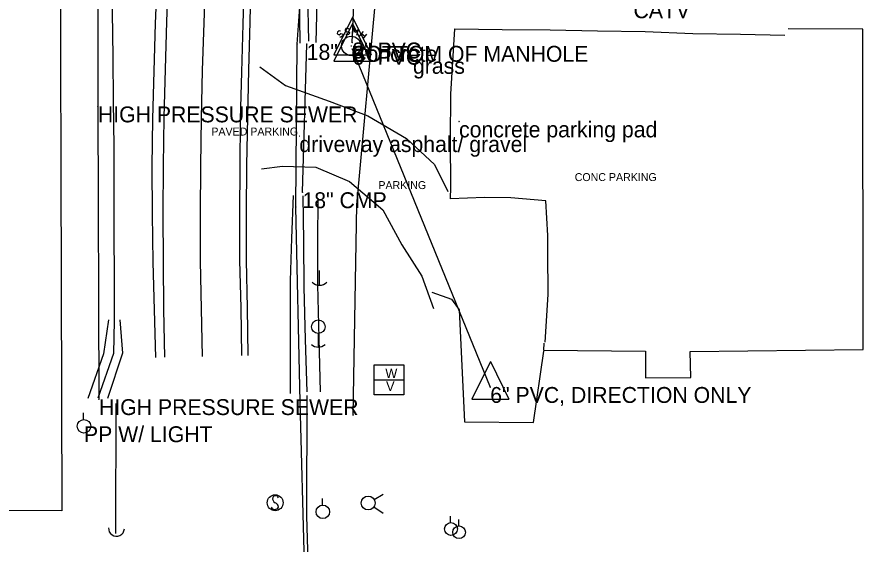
# Model space of a CAD drawing. Extents: x 1802180 to 1804859, y 572524 to 575172.
# Drawn here: x 1803144.4 to 1803410.8, y 572716.2 to 572882.1 of the extents above; entities that cross this region are included whole.
import ezdxf

# ---------------------------------------------------------------- set-up
doc = ezdxf.new("R2010")
doc.units = 0
for name, color, linetype in [('EX_EDGE_PAVEMENT', 7, 'Continuous'), ('S_CAL_CORNER', 7, 'Continuous'), ('S_CROSS_DRAIN', 7, 'Continuous'), ('S_DITCHLINE', 7, 'Continuous'), ('S_DRG_PT_SYM', 7, 'Continuous'), ('S_DRIVEWAY', 7, 'Continuous'), ('S_EDGE_CONCRETE', 7, 'Continuous'), ('S_GAS_UTILITIES', 7, 'Continuous'), ('S_MANHOLE_ANNOT', 7, 'Continuous'), ('S_MISC_BOUNDARY', 7, 'Continuous'), ('S_MSC_PT_SYM', 7, 'Continuous'), ('S_PARKING', 7, 'Continuous'), ('S_PARKING_ANNOT', 7, 'Continuous'), ('S_PAVEMENT_CROWN', 7, 'Continuous'), ('S_SANITARY_SEWER', 7, 'Continuous'), ('S_SANITARY_SEWER_ANNOT', 7, 'Continuous'), ('S_SHOULDER', 7, 'Continuous'), ('S_SIDE_DRAIN', 7, 'Continuous'), ('S_SIDE_DRAIN_ANNOT', 7, 'Continuous'), ('S_SIGN', 7, 'Continuous'), ('S_STREAM', 7, 'Continuous'), ('S_SURVEY_TEXT_ANNOT', 7, 'Continuous'), ('S_TELEPHONE_UTILITIES_ANNOT', 7, 'Continuous'), ('S_UTILITY_POLE', 7, 'Continuous'), ('S_UTILITY_POLE_ANNOT', 7, 'Continuous'), ('S_UTL_PT_SYM', 7, 'Continuous'), ('S_WATER_UTILITIES', 7, 'Continuous')]:
    doc.layers.add(name, color=color, linetype=linetype)

msp = doc.modelspace()

# ---------------------------------------------------------------- linework, layer by layer
at = {"layer": 'EX_EDGE_PAVEMENT'}
for points in [[(1803190.96, 572775), (1803190.67, 572789.99), (1803190.52, 572805.05), (1803190.47, 572820.24), (1803190.56, 572835.38), (1803190.74, 572850.48), (1803191.11, 572865.67), (1803191.56, 572880.57), (1803192.13, 572895.93), (1803192.98, 572910.91), (1803194.03, 572925.97), (1803195.31, 572941.25), (1803196.89, 572956.4), (1803198.72, 572971.29), (1803200.89, 572986.62), (1803203.33, 573001.42), (1803205.96, 573016.44)], [(1803229.77, 573012.09), (1803227.31, 572997.57), (1803224.82, 572982.77), (1803222.69, 572968.45), (1803220.88, 572953.56), (1803219.24, 572938.89), (1803217.94, 572924.29), (1803216.81, 572909.44), (1803215.9, 572894.47), (1803215.53, 572879.86), (1803215.04, 572864.77), (1803214.7, 572849.98), (1803214.58, 572835.08), (1803214.46, 572820.23), (1803214.48, 572805.43), (1803214.88, 572790.5), (1803215.12, 572775.5)]]:
    msp.add_lwpolyline(points, dxfattribs=at)
at = {"layer": 'S_CAL_CORNER'}
for p, q in [((1803250.06, 572882.03), (1803244.18, 572870.21)), ((1803250.06, 572882.03), (1803255.87, 572870.21)), ((1803250.07, 572880.04), (1803244.2, 572868.22)), ((1803250.07, 572880.04), (1803255.89, 572868.22)), ((1803244.18, 572870.21), (1803255.87, 572870.21)), ((1803244.2, 572868.22), (1803255.89, 572868.22)), ((1803293.5, 572773.61), (1803287.62, 572761.79)), ((1803293.5, 572773.61), (1803299.31, 572761.79)), ((1803287.62, 572761.79), (1803299.31, 572761.79))]:
    msp.add_line(p, q, dxfattribs=at)
at = {"layer": 'S_CROSS_DRAIN'}
msp.add_arc((1803175.71, 572721.17), 2.5, 175.9715, 356.3007, dxfattribs=at)
at = {"layer": 'S_DITCHLINE'}
for points in [[(1803191.07, 573030.48), (1803186.39, 573007.51), (1803182.91, 572995.28), (1803179.43, 572983.05), (1803177.62, 572967.17), (1803175.82, 572951.28), (1803175.41, 572937.89), (1803175, 572924.5), (1803174.59, 572911.11), (1803174.18, 572897.72), (1803174.36, 572883.63), (1803174.53, 572869.54), (1803174.71, 572855.44), (1803174.88, 572841.35), (1803174.91, 572827.64), (1803174.93, 572813.93), (1803174.96, 572800.22), (1803174.98, 572786.51), (1803174.73, 572776.19), (1803169.82, 572762.15)], [(1803233.51, 572873.82), (1803233.22, 572897.98), (1803232.93, 572922.13), (1803234.68, 572936.13), (1803236.43, 572950.13), (1803238.18, 572964.13), (1803239.93, 572978.13), (1803245.22, 572978.79), (1803243.9, 572965.52), (1803242.57, 572952.24), (1803241.24, 572938.96), (1803239.92, 572925.69), (1803239.56, 572912.78), (1803239.2, 572899.88), (1803238.85, 572886.98), (1803238.49, 572874.08)], [(1803236.24, 572874.49), (1803236.01, 572889.51), (1803235.77, 572904.52), (1803237.65, 572923.02), (1803239.52, 572941.52), (1803241.39, 572960.03), (1803243.27, 572978.53)], [(1803230.47, 572763.54), (1803230.47, 572781.28), (1803230.47, 572799.02), (1803230.97, 572812.47), (1803231.47, 572825.91)], [(1803235.72, 572764.15), (1803235.27, 572780.61), (1803234.82, 572797.08), (1803234.66, 572811.43), (1803234.5, 572825.79)], [(1803239.92, 572764.15), (1803239.51, 572780.96), (1803239.09, 572797.77), (1803239.17, 572811.39), (1803239.26, 572825.02)], [(1803173.21, 572786.75), (1803171.64, 572776.07), (1803166.65, 572762.03)], [(1803176.73, 572786.81), (1803177.62, 572776.32), (1803172.87, 572761.98)]]:
    msp.add_lwpolyline(points, dxfattribs=at)
at = {"layer": 'S_DRG_PT_SYM'}
for points in [[(1803235.61, 572873.58), (1803235.61, 572873.63), (1803235.61, 572873.58), (1803235.56, 572873.58), (1803235.61, 572873.58), (1803235.61, 572873.53), (1803235.61, 572873.58), (1803235.66, 572873.58)], [(1803234.28, 572826.92), (1803234.28, 572826.97), (1803234.28, 572826.92), (1803234.23, 572826.92), (1803234.28, 572826.92), (1803234.28, 572826.87), (1803234.28, 572826.92), (1803234.33, 572826.92)]]:
    msp.add_lwpolyline(points, dxfattribs=at)
at = {"layer": 'S_DRIVEWAY'}
for points in [[(1803220.82, 572866.42), (1803228.99, 572860.55), (1803242.69, 572855.6), (1803254.84, 572851.01), (1803267.09, 572843.85), (1803275.87, 572835.62), (1803280.1, 572827.12)], [(1803221.41, 572834.28), (1803228.01, 572835.09), (1803238.54, 572834.78), (1803249.05, 572830.36), (1803259.62, 572821.4), (1803265.55, 572810.43), (1803271.85, 572800.55), (1803275.51, 572790.3)]]:
    msp.add_lwpolyline(points, dxfattribs=at)
at = {"layer": 'S_EDGE_CONCRETE'}
msp.add_lwpolyline([(1803310.71, 572779.78), (1803311.69, 572794.76), (1803311.58, 572807.87), (1803311.51, 572813.36), (1803310.95, 572824.26), (1803299.9, 572825.13), (1803291.56, 572825.27), (1803280.86, 572824.89), (1803281.03, 572828.54), (1803280.86, 572843.54), (1803280.95, 572857.79), (1803282.25, 572878.37), (1803297.21, 572878.13), (1803312.23, 572878.09), (1803327.23, 572877.77), (1803342.23, 572877.52), (1803357.22, 572876.93), (1803372.2, 572876.67), (1803386.12, 572876.33)], dxfattribs=at)
at = {"layer": 'S_GAS_UTILITIES'}
for p, q in [((1803232.66, 572873.56), (1803239.64, 572977.11)), ((1803232.24, 572822.25), (1803232.66, 572873.56)), ((1803233.57, 572760.94), (1803232.24, 572822.25)), ((1803235.4, 572692.72), (1803233.57, 572760.94))]:
    msp.add_line(p, q, dxfattribs=at)
at = {"layer": 'S_MISC_BOUNDARY'}
msp.add_lwpolyline([(1802880.88, 573735.6), (1803051.71, 573733.48), (1803213.27, 573730.83), (1803216.46, 573532.09), (1803301.63, 573530.07), (1803296.75, 573432.28), (1803274.96, 573355.36), (1803226.68, 573219.53), (1803202.19, 573137.5), (1803157.77, 572977.33), (1803158.5, 572726.69), (1802889.88, 572728.1)], dxfattribs=at)
at = {"layer": 'S_MSC_PT_SYM'}
for points in [[(1803269.08, 572869.21), (1803269.08, 572869.26), (1803269.08, 572869.21), (1803269.03, 572869.21), (1803269.08, 572869.21), (1803269.08, 572869.16), (1803269.08, 572869.21), (1803269.13, 572869.21)], [(1803283.58, 572849.2), (1803283.58, 572849.25), (1803283.58, 572849.2), (1803283.53, 572849.2), (1803283.58, 572849.2), (1803283.58, 572849.15), (1803283.58, 572849.2), (1803283.63, 572849.2)], [(1803233.3, 572844.58), (1803233.3, 572844.63), (1803233.3, 572844.58), (1803233.25, 572844.58), (1803233.3, 572844.58), (1803233.3, 572844.53), (1803233.3, 572844.58), (1803233.35, 572844.58)]]:
    msp.add_lwpolyline(points, dxfattribs=at)
at = {"layer": 'S_PARKING'}
for points in [[(1803410.81, 572777.43), (1803410.71, 572878.28), (1803387.24, 572878.36)], [(1803275, 572795.47), (1803281.17, 572793.24), (1803283.63, 572789.91), (1803285.33, 572754.66), (1803307.06, 572754.43), (1803310.26, 572776.94)], [(1803310.24, 572779.44), (1803310.23, 572777.19), (1803342.25, 572776.94), (1803342.29, 572768.49), (1803356.61, 572768.6), (1803356.39, 572776.77), (1803410.81, 572777.43)]]:
    msp.add_lwpolyline(points, dxfattribs=at)
at = {"layer": 'S_PAVEMENT_CROWN'}
msp.add_lwpolyline([(1803202.77, 572775.24), (1803202.46, 572790.24), (1803202.2, 572805.24), (1803202.14, 572820.24), (1803202.26, 572835.24), (1803202.49, 572850.23), (1803202.85, 572865.23), (1803203.36, 572880.22), (1803203.81, 572895.21), (1803204.74, 572910.18), (1803205.78, 572925.15), (1803207.14, 572940.08), (1803208.7, 572955), (1803210.47, 572969.9), (1803212.51, 572984.75), (1803214.89, 572999.56), (1803217.53, 573014.33)], dxfattribs=at)
at = {"layer": 'S_SANITARY_SEWER'}
for p, q in [((1803249.97, 572874.05), (1803253.55, 572967.87)), ((1803169.74, 572919.36), (1803169.86, 572853.93)), ((1803245.31, 572877.3), (1803245.23, 572876.91)), ((1803245.23, 572876.91), (1803245.42, 572876.64)), ((1803245.85, 572877.69), (1803245.31, 572877.3)), ((1803245.42, 572876.64), (1803245.85, 572876.52)), ((1803246.28, 572877.61), (1803245.85, 572877.69)), ((1803245.85, 572876.52), (1803246.39, 572876.87)), ((1803246.39, 572875.71), (1803246, 572875.79)), ((1803246.39, 572876.87), (1803246.86, 572876.8)), ((1803246.93, 572876.1), (1803246.39, 572875.71)), ((1803246.86, 572876.8), (1803247.01, 572876.52)), ((1803247.01, 572876.52), (1803246.93, 572876.1)), ((1803252.28, 572876.06), (1803253.52, 572877.53)), ((1803252.94, 572876.83), (1803253.91, 572876.02)), ((1803254.49, 572876.72), (1803253.25, 572875.25)), ((1803249.98, 572872.06), (1803293.41, 572765.63)), ((1803169.86, 572853.93), (1803170.2, 572761.8))]:
    msp.add_line(p, q, dxfattribs=at)
for points in [[(1803248.95, 572878.23), (1803248.6, 572878.5), (1803247.94, 572878.42), (1803247.71, 572878.07), (1803247.75, 572877.76), (1803248.1, 572877.45), (1803248.72, 572877.57), (1803249.1, 572877.26), (1803249.14, 572876.95), (1803248.87, 572876.56), (1803248.25, 572876.49), (1803247.9, 572876.76)], [(1803251.39, 572876.37), (1803251.93, 572878.23), (1803250.89, 572877.22), (1803250.5, 572878.66), (1803249.96, 572876.8)]]:
    msp.add_lwpolyline(points, dxfattribs=at)
msp.add_circle((1803249.63, 572873), 3.05, dxfattribs=at)
at = {"layer": 'S_SHOULDER'}
for points in [[(1803188.06, 572774.94), (1803187.64, 572789.93), (1803187.25, 572804.96), (1803187.05, 572819.98), (1803186.96, 572835.01), (1803187.13, 572850.03), (1803187.6, 572865.07), (1803188.05, 572880.08), (1803188.63, 572895.09), (1803189.46, 572910.14), (1803190.47, 572925.15), (1803191.68, 572940.15), (1803193.18, 572955.14), (1803195.08, 572970.09), (1803197.21, 572985), (1803199.42, 572999.92), (1803202, 573014.73), (1803204.73, 573029.52), (1803207.64, 573044.28), (1803210.93, 573059.01), (1803214.56, 573073.63), (1803217.45, 573083.45)], [(1803217.19, 572775.54), (1803216.95, 572790.56), (1803216.67, 572805.5), (1803216.65, 572820.48), (1803216.72, 572835.48), (1803217.08, 572850.44), (1803217.44, 572865.41), (1803217.82, 572880.43), (1803218.13, 572895.35), (1803219.14, 572910.28), (1803220.26, 572925.21), (1803221.76, 572940.08), (1803223.21, 572954.99), (1803224.98, 572969.82), (1803227.01, 572984.65), (1803229.31, 572999.47), (1803231.85, 573014.23), (1803234.7, 573028.93), (1803237.73, 573043.58), (1803241.04, 573058.18), (1803243.89, 573069.48), (1803244.54, 573072.71)]]:
    msp.add_lwpolyline(points, dxfattribs=at)
at = {"layer": 'S_SIDE_DRAIN'}
msp.add_line((1803234.28, 572826.92), (1803235.61, 572873.58), dxfattribs=at)
at = {"layer": 'S_SIGN'}
msp.add_circle((1803225.7, 572729.21), 2.5, dxfattribs=at)
for centre, radius, start, end in [((1803225.78, 572730.48), 0.952, 16.5258, 156.8957), ((1803226.39, 572730.54), 1.51, 167.1196, 241.9813), ((1803225.29, 572727.87), 1.4, 358.6529, 73.7063), ((1803225.55, 572728.39), 1.28, 204.641, 335.359)]:
    msp.add_arc(centre, radius, start, end, dxfattribs=at)
at = {"layer": 'S_STREAM'}
for points in [[(1803237.8, 572598.96), (1803237.64, 572657), (1803235.61, 572725.12), (1803235.72, 572762.98)], [(1803175.48, 572719.49), (1803175.66, 572760.41)]]:
    msp.add_lwpolyline(points, dxfattribs=at)
at = {"layer": 'S_UTILITY_POLE'}
for p, q in [((1803239.58, 572802.35), (1803239.58, 572797.62)), ((1803239.25, 572782.42), (1803239.25, 572778.18)), ((1803165.36, 572755.41), (1803165.36, 572757.52)), ((1803240.56, 572728.49), (1803240.56, 572730.59)), ((1803280.94, 572722.95), (1803280.94, 572724.94)), ((1803283.49, 572721.91), (1803283.49, 572723.89))]:
    msp.add_line(p, q, dxfattribs=at)
for centre, radius in [((1803239.25, 572784.6), 2.13), ((1803165.48, 572753.27), 2.13), ((1803240.68, 572726.34), 2.13), ((1803281.05, 572720.94), 2), ((1803283.61, 572719.9), 2)]:
    msp.add_circle(centre, radius, dxfattribs=at)
for centre, radius in [((1803239.64, 572801.05), 3.41), ((1803239.25, 572781.29), 3.09)]:
    msp.add_arc(centre, radius, 226.3972, 313.6028, dxfattribs=at)
at = {"layer": 'S_UTL_PT_SYM'}
for points in [[(1803232.66, 572873.56), (1803232.66, 572873.61), (1803232.66, 572873.56), (1803232.61, 572873.56), (1803232.66, 572873.56), (1803232.66, 572873.51), (1803232.66, 572873.56), (1803232.71, 572873.56)], [(1803249.65, 572873), (1803249.65, 572873.05), (1803249.65, 572873), (1803249.6, 572873), (1803249.65, 572873), (1803249.65, 572872.95), (1803249.65, 572873), (1803249.7, 572873)], [(1803249.97, 572874.05), (1803249.97, 572874.1), (1803249.97, 572874.05), (1803249.92, 572874.05), (1803249.97, 572874.05), (1803249.97, 572874), (1803249.97, 572874.05), (1803250.02, 572874.05)], [(1803249.98, 572872.06), (1803249.98, 572872.11), (1803249.98, 572872.06), (1803249.93, 572872.06), (1803249.98, 572872.06), (1803249.98, 572872.01), (1803249.98, 572872.06), (1803250.03, 572872.06)], [(1803169.86, 572853.93), (1803169.86, 572853.98), (1803169.86, 572853.93), (1803169.81, 572853.93), (1803169.86, 572853.93), (1803169.86, 572853.88), (1803169.86, 572853.93), (1803169.91, 572853.93)], [(1803232.24, 572822.25), (1803232.24, 572822.3), (1803232.24, 572822.25), (1803232.19, 572822.25), (1803232.24, 572822.25), (1803232.24, 572822.2), (1803232.24, 572822.25), (1803232.29, 572822.25)], [(1803251.42, 572822.92), (1803251.42, 572822.97), (1803251.42, 572822.92), (1803251.37, 572822.92), (1803251.42, 572822.92), (1803251.42, 572822.87), (1803251.42, 572822.92), (1803251.47, 572822.92)], [(1803293.41, 572765.63), (1803293.41, 572765.68), (1803293.41, 572765.63), (1803293.36, 572765.63), (1803293.41, 572765.63), (1803293.41, 572765.58), (1803293.41, 572765.63), (1803293.46, 572765.63)], [(1803170.2, 572761.8), (1803170.2, 572761.85), (1803170.2, 572761.8), (1803170.15, 572761.8), (1803170.2, 572761.8), (1803170.2, 572761.75), (1803170.2, 572761.8), (1803170.25, 572761.8)], [(1803233.57, 572760.94), (1803233.57, 572760.99), (1803233.57, 572760.94), (1803233.52, 572760.94), (1803233.57, 572760.94), (1803233.57, 572760.89), (1803233.57, 572760.94), (1803233.62, 572760.94)], [(1803250.21, 572756.81), (1803250.21, 572756.86), (1803250.21, 572756.81), (1803250.16, 572756.81), (1803250.21, 572756.81), (1803250.21, 572756.76), (1803250.21, 572756.81), (1803250.26, 572756.81)]]:
    msp.add_lwpolyline(points, dxfattribs=at)
at = {"layer": 'S_WATER_UTILITIES'}
for p, q in [((1803251.42, 572822.92), (1803262.53, 572945.13)), ((1803250.21, 572756.81), (1803251.42, 572822.92)), ((1803256.82, 572772.6), (1803266.24, 572772.6)), ((1803256.82, 572763.18), (1803256.82, 572772.6)), ((1803266.24, 572772.6), (1803266.24, 572763.18)), ((1803256.82, 572767.91), (1803266.24, 572767.91)), ((1803266.24, 572763.18), (1803256.82, 572763.18)), ((1803256.89, 572730.18), (1803259.71, 572731.91)), ((1803256.76, 572727.87), (1803259.67, 572725.94))]:
    msp.add_line(p, q, dxfattribs=at)
msp.add_circle((1803254.98, 572729.12), 2.18, dxfattribs=at)

# ---------------------------------------------------------------- texts
at = {"layer": 'S_MANHOLE_ANNOT'}
msp.add_text('BOTTOM OF MANHOLE', height=5, dxfattribs=at).set_placement((1803249.65, 572868))
at = {"layer": 'S_PARKING_ANNOT'}
for s, p in [('PAVED PARKING', (1803205.6, 572844.79)), ('CONC PARKING', (1803320.01, 572830.45)), ('PARKING', (1803258.19, 572827.93))]:
    msp.add_text(s, height=2.5, dxfattribs=at).set_placement(p)
at = {"layer": 'S_SANITARY_SEWER_ANNOT'}
for s, p in [('Concrete', (1803249.63, 572868)), ('8" PVC', (1803249.97, 572869.05)), ('6" PVC', (1803249.98, 572867.06)), ('HIGH PRESSURE SEWER  ', (1803169.86, 572848.93)), ('6" PVC, DIRECTION ONLY  ', (1803293.41, 572760.63)), ('HIGH PRESSURE SEWER  ', (1803170.2, 572756.8))]:
    msp.add_text(s, height=5, dxfattribs=at).set_placement(p)
at = {"layer": 'S_SIDE_DRAIN_ANNOT'}
for s, p in [('18"       ', (1803235.61, 572868.58)), ('18" CMP', (1803234.28, 572821.92))]:
    msp.add_text(s, height=5, dxfattribs=at).set_placement(p)
at = {"layer": 'S_SURVEY_TEXT_ANNOT'}
for s, p in [('grass', (1803269.08, 572864.21)), ('concrete parking pad', (1803283.58, 572844.2)), ('driveway asphalt/ gravel', (1803233.3, 572839.58))]:
    msp.add_text(s, height=5, dxfattribs=at).set_placement(p)
at = {"layer": 'S_TELEPHONE_UTILITIES_ANNOT'}
msp.add_text('CATV ', height=5, dxfattribs=at).set_placement((1803338.51, 572881.71))
at = {"layer": 'S_UTILITY_POLE_ANNOT'}
msp.add_text('PP W/ LIGHT', height=5, dxfattribs=at).set_placement((1803165.48, 572748.27))
at = {"layer": 'S_WATER_UTILITIES'}
for s, p in [('W', (1803260.37, 572768.44)), ('V', (1803260.61, 572764.38))]:
    msp.add_text(s, height=3, rotation=360, dxfattribs=at).set_placement(p)

doc.saveas('drawing.dxf')
